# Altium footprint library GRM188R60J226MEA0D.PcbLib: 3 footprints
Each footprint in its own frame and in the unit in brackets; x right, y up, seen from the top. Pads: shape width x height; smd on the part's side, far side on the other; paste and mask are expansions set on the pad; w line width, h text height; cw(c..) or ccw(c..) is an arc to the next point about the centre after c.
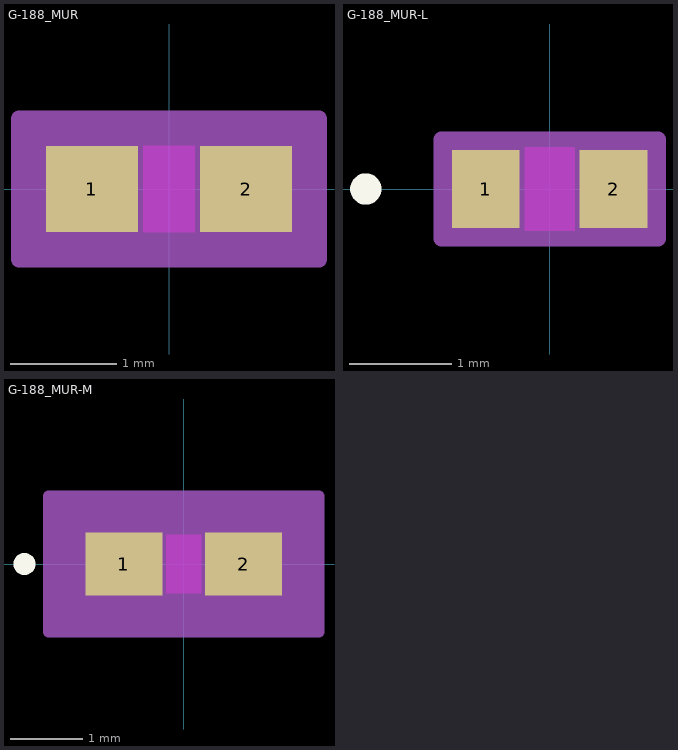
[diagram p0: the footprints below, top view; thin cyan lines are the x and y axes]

## G-188_MUR [mil]
pads (2):
  rect 34x32 smd paste+0 mask+0: 1(-28.5,0) 2(28.5,0)
Top Layer keep-out:
  region: -9.5,-14 -9.5,14 9.5,14 9.5,-14
Top Overlay:
  text ".Designator" at -137.5,-25 h50
Keep-Out Layer:
  region: -9.5,-16 -9.5,16 9.5,16 9.5,-16
Mechanical 13:
  circle w1: c-23.5,0 r0
  lines w1: -31.5,-16 -31.5,16 ; -31.5,-16 -11.5,-16 -11.5,16 -31.5,16 ; -31.5,-16 31.5,-16 ; -31.5,-16 -31.5,16 ; -31.5,16 31.5,16 ; 31.5,-16 11.5,-16 11.5,16 31.5,16 ; 31.5,-16 31.5,16 ; 31.5,-16 31.5,16
  text ".Designator" at -137.5,-25 h50
Mechanical 15:
  region: 55.5,-26 -55.5,-26 -55.5,26 55.5,26
  lines w6: -55.5,-26 -55.5,26 55.5,26 55.5,-26 -55.5,-26
3D body "G-188_MUR.step": height 35, standoff 0, extent -31.5,-15.98 31.5,15.98

## G-188_MUR-L [mil]
pads (2):
  rect 26x30 smd paste+0 mask+0: 1(-24.5,0) 2(24.5,0)
Top Layer keep-out:
  region: -9.5,-14 -9.5,14 9.5,14 9.5,-14
Top Overlay:
  circle w6: c-70.5,0 r3
  text ".Designator" at -137.5,-25 h50
Keep-Out Layer:
  region: -9.5,-16 -9.5,16 9.5,16 9.5,-16
Mechanical 13:
  circle w1: c-19.5,0 r3
  lines w1: -31.5,-16 -31.5,16 ; -31.5,-16 -11.5,-16 -11.5,16 -31.5,16 ; -31.5,-16 31.5,-16 ; -31.5,-16 -31.5,16 ; -31.5,16 31.5,16 ; 31.5,-16 11.5,-16 11.5,16 31.5,16 ; 31.5,-16 31.5,16 ; 31.5,-16 31.5,16
  text ".Designator" at -137.5,-25 h50
Mechanical 15:
  region: 41.5,-19 -41.5,-19 -41.5,19 41.5,19
  lines w6: -41.5,-19 -41.5,19 41.5,19 41.5,-19 -41.5,-19
3D body "G-188_MUR.step": height 35, standoff 0, extent -31.5,-15.98 31.5,15.98

## G-188_MUR-M [mil]
pads (2):
  rect 42x34 smd paste+0 mask+0: 1(-32.5,0) 2(32.5,0)
Top Layer keep-out:
  region: -9.5,-14 -9.5,14 9.5,14 9.5,-14
Top Overlay:
  circle w6: c-86.5,0 r3
  text ".Designator" at -137.5,-25 h50
Keep-Out Layer:
  region: -9.5,-16 -9.5,16 9.5,16 9.5,-16
Mechanical 13:
  circle w1: c-27.5,0 r3
  lines w1: -31.5,-16 -31.5,16 ; -31.5,-16 -11.5,-16 -11.5,16 -31.5,16 ; -31.5,-16 31.5,-16 ; -31.5,-16 -31.5,16 ; -31.5,16 31.5,16 ; 31.5,-16 11.5,-16 11.5,16 31.5,16 ; 31.5,-16 31.5,16 ; 31.5,-16 31.5,16
  text ".Designator" at -137.5,-25 h50
Mechanical 15:
  region: 73.5,-37 -73.5,-37 -73.5,37 73.5,37
  lines w6: -73.5,-37 -73.5,37 73.5,37 73.5,-37 -73.5,-37
3D body "G-188_MUR.step": height 35, standoff 0, extent -31.5,-15.98 31.5,15.98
